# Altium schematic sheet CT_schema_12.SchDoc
size 274 x 160 mm
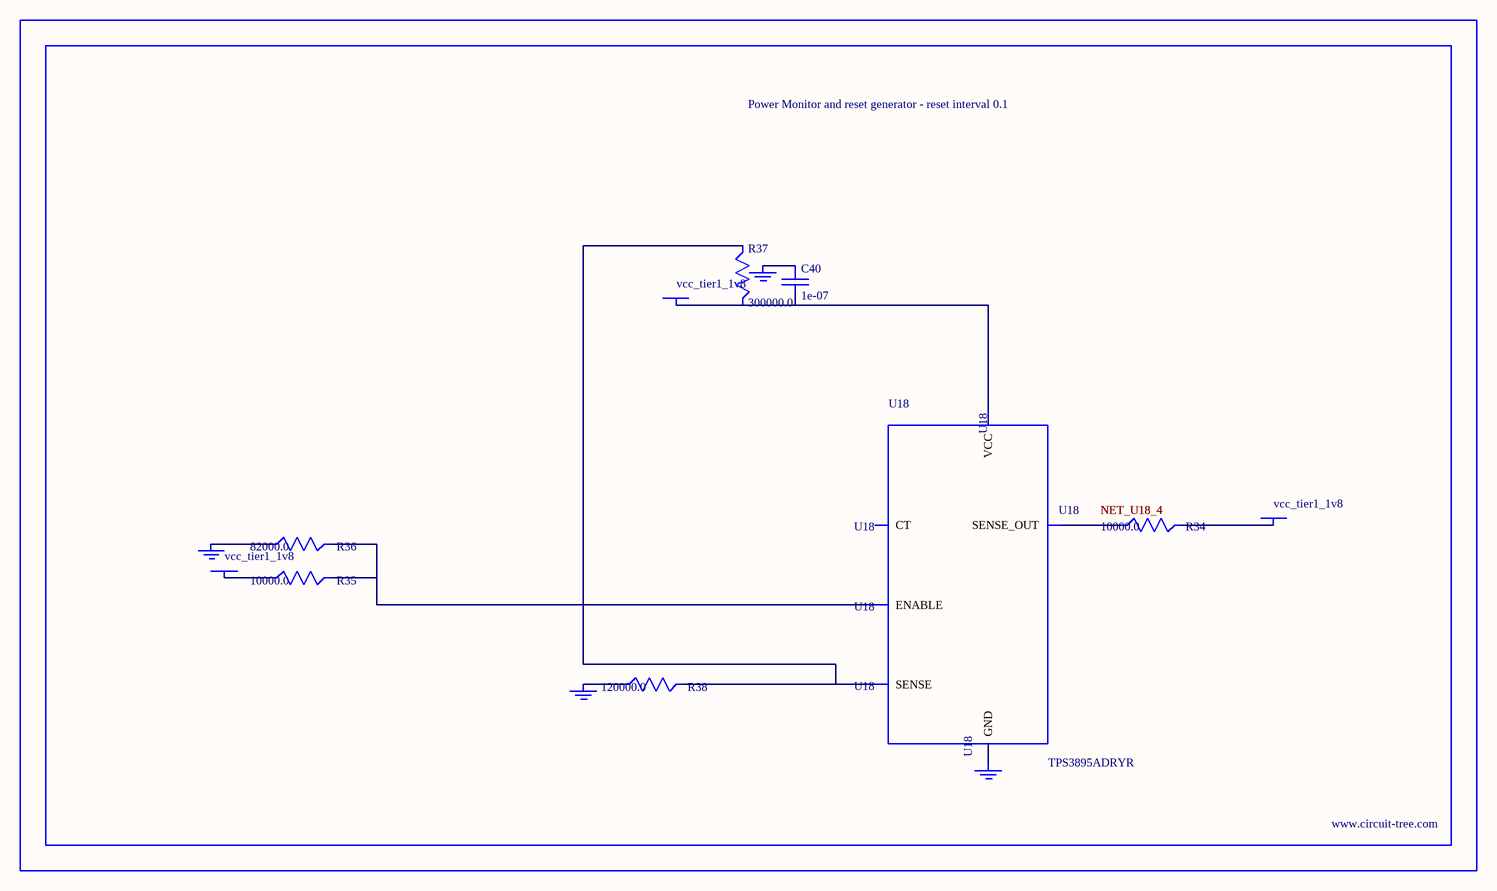
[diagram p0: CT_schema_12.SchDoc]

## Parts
BORDER11  (no value)
C40  1e-07  [C0402]
GND_INSTANCE_11_0  (no value)
GND_INSTANCE_11_1  (no value)
GND_INSTANCE_11_2  (no value)
GND_INSTANCE_11_3  (no value)
POWER_INSTANCE_11_0  vcc_tier1_1v8
POWER_INSTANCE_11_1  vcc_tier1_1v8
POWER_INSTANCE_11_2  vcc_tier1_1v8
R34  10000.0  [R0603]
R35  10000.0  [R0603]
R36  82000.0  [R0603]
R37  300000.0  [R0603]
R38  120000.0  [R0603]
U18  TPS3895ADRYR  [SON-6]

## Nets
NetC40_1: C40.1 GND_INSTANCE_11_2.0(GND)
NetC40_2: C40.2 POWER_INSTANCE_11_2.0(PWR) R37.2 U18.6(VCC)
NetGND_INSTANCE_11_0_0: GND_INSTANCE_11_0.0(GND) R36.1
NetGND_INSTANCE_11_1_0: GND_INSTANCE_11_1.0(GND) R38.1
NetGND_INSTANCE_11_3_0: GND_INSTANCE_11_3.0(GND) U18.2(GND)
NetPOWER_INSTANCE_11_0_0: POWER_INSTANCE_11_0.0(PWR) R35.1
NetPOWER_INSTANCE_11_1_0: POWER_INSTANCE_11_1.0(PWR) R34.2
NetR34_1: R34.1 U18.4(SENSE_OUT)
NetR35_2: R35.2 R36.2 U18.1(ENABLE)
NetR37_1: R37.1 R38.2 U18.3(SENSE)

Not connected (* = marked no-connect by the designer): U18 5(CT)

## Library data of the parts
BORDER11 = BORDER_PAGE11
C40 = C0402C104K3RACTU
GND_INSTANCE_11_0-GND_INSTANCE_11_3 = GND
POWER_INSTANCE_11_0-POWER_INSTANCE_11_2 = PWR
R34 R35 = RC0603JR-0710KL
R36 = RC0603JR-0782KL
R37 = RC0603JR-07300KL
R38 = RC0603JR-07120KL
